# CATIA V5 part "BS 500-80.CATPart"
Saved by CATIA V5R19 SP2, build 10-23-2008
Part number: BS 500-80
Bounding box of the stored display mesh (mm): x -18.951 to 18.951, y -18.952 to 18.952, z 0 to 190
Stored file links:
  C:\Users\Bora\Desktop\3D Katı model\BS serisi\BS 500\BS 500-80.CATPart
  C:\Program Files\Dassault Systemes\B19\intel_a\reffiles\standard\MetricThickPitch.txt
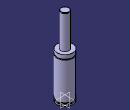
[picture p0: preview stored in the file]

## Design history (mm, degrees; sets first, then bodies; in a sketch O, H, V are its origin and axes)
Body1 (main body)
  Sketch1 on yz-plane, origin (0, 0, 0), H (0, 1, 0), V (0, 0, 1)
    point P1 (10, 189)
    point P3 (10, 189)
    point P5 (19, 99.5)
    point P6 (19, 97.5)
    point P9 (19, 99.5)
    point P14 (19, 97.5)
    line L1 (10, 189) -> (10, 109)
    arc A1 centre (9, 189) radius 1 from (10, 189) to (9, 190) ccw
    arc A2 centre (19, 98.5) radius 1 from (19, 99.5) to (19, 97.5) ccw
    line L2 (19, 0) -> (19, 4)
    line L3 (19, 99.5) -> (19, 109)
    line L4 (17, 7.5) -> (17, 4)
    line L5 (19, 7.5) -> (19, 97.5)
    line L6 (9, 190) -> (0, 190)
    point P15 (0, 190)
    line L7 (10, 109) -> (19, 109)
    line L8 (0, 0) -> (19, 0)
    line L9 (17, 7.5) -> (19, 7.5)
    line L10 (17, 4) -> (19, 4)
    coincidence: P15 V, P1 P3, P5 P9, P6 P14
    tangency: L6 A1
    horizontal: L7 H, L8 H, L9 H, L10 H
  Shaft1: profile Sketch1, axis Sketch1.V, angle 360
  Sketch2 on face of Shaft1 from Sketch1.L8, origin (0, 0, 0), H (1, 0, 0), V (0, -1, 0)
    point P1 (0, 0)
  Hole1: placed by Sketch2, at (0, 0, 0) direction (0, 0, 1), diameter 6.647, depth 4, threaded "M8", thread diameter 8, thread depth 4, pitch 1.25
